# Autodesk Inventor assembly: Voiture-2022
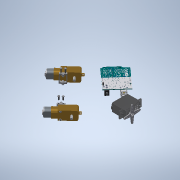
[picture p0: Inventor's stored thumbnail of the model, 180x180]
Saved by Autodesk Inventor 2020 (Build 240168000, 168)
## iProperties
Created: 2018-03
Part Number: Voiture-2022
Material: Générique
Document SubType Name: Assembly
Designer: Bruno
Author: Bruno
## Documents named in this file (4)
- C:\Users\bruno\OneDrive\Bureau\Voiture-Inventor\Voiture-2022.iam
- C:\Users\bruno\OneDrive\Bureau\Voiture-Inventor\Roue.iam
- C:\Users\bruno\OneDrive\Bureau\Voiture-Inventor\Bati-Voiture.iam
- C:\Users\bruno\OneDrive\Bureau\Voiture-Inventor\attache-servo.ipt
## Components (4 placed, 3 different names)
1. Roue:1 [sub-assembly] — Placage:1, Affleurement:1
2. Roue:2 [sub-assembly] — Placage:2, Affleurement:2
3. Bati-Voiture:1 [sub-assembly] — Placage:1, Placage:2, Affleurement:1, Affleurement:2, Logement:1
4. attache-servo:1 — Logement:1
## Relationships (5: Mate 2, Flush 2, Insert 1)
- Placage:1 [Mate]: Roue:1 ↔ Bati-Voiture:1
- Placage:2 [Mate]: Roue:2 ↔ Bati-Voiture:1
- Affleurement:1 [Flush]: Roue:1 ↔ Bati-Voiture:1
- Affleurement:2 [Flush]: Roue:2 ↔ Bati-Voiture:1
- Logement:1 [Insert]: Bati-Voiture:1 ↔ attache-servo:1
